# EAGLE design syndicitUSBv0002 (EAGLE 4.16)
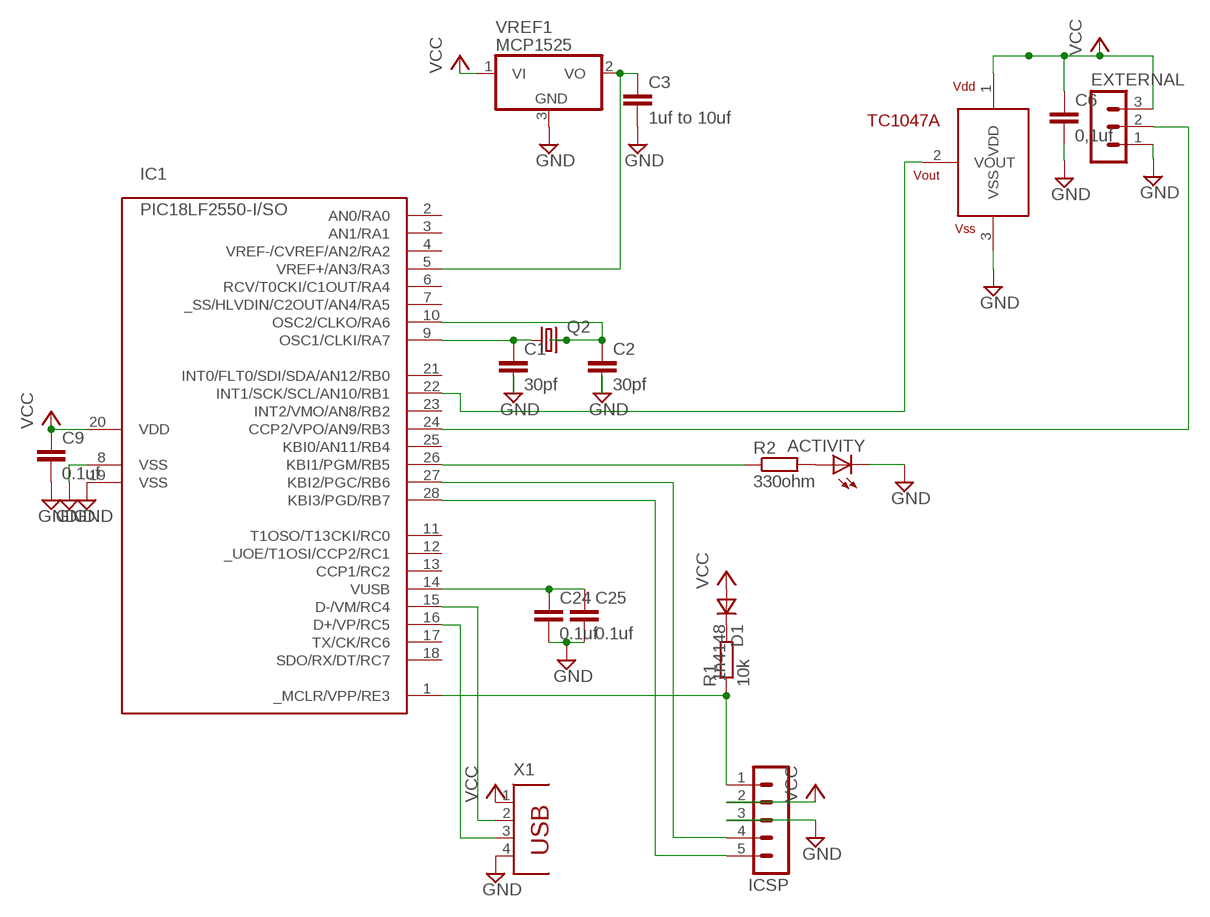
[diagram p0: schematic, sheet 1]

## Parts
ACTIVITY  LEDCHIPLED_1206  [CHIPLED_1206]
C1  30pf  C-EUC0805K  [C0805K]
C2  30pf  C-EUC0805K  [C0805K]
C3  1uf to 10uf  C-EUC0805K  [C0805K]
C6  0,1uf  C-EUC0805  [C0805]
C9  0.1uf  C-EUC0805K  [C0805K]
C24  0.1uf  C-EUC0805K  [C0805K]
C25  0.1uf  C-EUC0805K  [C0805K]
D1  1n4148  DSOT23  [SOT-23]
EXTERNAL  MA03-1  [MA03-1]
IC1  PIC18LF2550-I/SO  [SO-28W]
ICSP  MA05-1  [MA05-1]
Q2  CRYTALHC49UP  [HC49UP]
R1  10k  R-EU_R1206  [R1206]
R2  330ohm  R-EU_R0805  [R0805]
TC1047A  TC1047A  [SOT23B]
VREF1  MCP1525  MCP1525-SOT23  [SOT23]
X1  PN61729  [PN61729]

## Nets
GND: ACTIVITY.C C1.2 C2.2 C3.2 C6.2 C9.2 C24.2 C25.2 EXTERNAL.1 IC1.8(VSS) IC1.19(VSS) ICSP.3 TC1047A.3(VSS) VREF1.3(GND) X1.4
N$1: C1.1 IC1.9(OSC1/CLKI/RA7) Q2.1
N$2: C2.1 IC1.10(OSC2/CLKO/RA6) Q2.2
N$5: C24.1 C25.1 IC1.14(VUSB)
N$6: C3.1 IC1.5(VREF+/AN3/RA3) VREF1.2(VO)
N$7: IC1.27(KBI2/PGC/RB6) ICSP.4
N$8: IC1.28(KBI3/PGD/RB7) ICSP.5
N$9: D1.1(C) R1.2
N$10: IC1.1(_MCLR/VPP/RE3) ICSP.1 R1.1
N$11: EXTERNAL.2 IC1.24(CCP2/VPO/AN9/RB3)
N$12: ACTIVITY.A R2.2
N$14: IC1.26(KBI1/PGM/RB5) R2.1
N$23: IC1.15(D-/VM/RC4) X1.2
N$24: IC1.16(D+/VP/RC5) X1.3
N$44: IC1.22(INT1/SCK/SCL/AN10/RB1) TC1047A.2(VOUT)
VCC: C6.1 C9.1 D1.3(A) EXTERNAL.3 IC1.20(VDD) ICSP.2 TC1047A.1(VDD) VREF1.1(VI) X1.1
Unconnected: IC1.2(AN0/RA0) IC1.3(AN1/RA1) IC1.4(VREF-/CVREF/AN2/RA2) IC1.6(RCV/T0CKI/C1OUT/RA4) IC1.7(_SS/HLVDIN/C2OUT/AN4/RA5) IC1.11(T1OSO/T13CKI/RC0) IC1.12(_UOE/T1OSI/CCP2/RC1) IC1.13(CCP1/RC2) IC1.17(TX/CK/RC6) IC1.18(SDO/RX/DT/RC7) IC1.21(INT0/FLT0/SDI/SDA/AN12/RB0) IC1.23(INT2/VMO/AN8/RB2) IC1.25(KBI0/AN11/RB4)

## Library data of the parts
ACTIVITY = led:LED: LED
C1-C3 C6 C9 C24 C25 = rcl:C-EU: CAPACITOR, European symbol
D1 = zetex:D: DIODE
EXTERNAL = con-lstb:MA03-1: PIN HEADER
IC1 = microchip-pic18fxx5x:PIC18*2550: PIC18*2550 Microchip FLASH Microcontroller with FS-USB DEVICE FEATURES FeaturePIC18*2550 Program Memory (bytes) 32k Program Memory (instructions) 16384 I/O Ports Ports A, B, C, (E) Capture/Compare/PWM Modules 2 Enhanced Capture/Compare/PWM Modules 0 Parallel Communications (PSP) No 10-bit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
ICSP = con-lstb:MA05-1: PIN HEADER
Q2 = crystal:CRYTAL: CRYSTAL
R1 R2 = rcl:R-EU_: RESISTOR, European symbol
TC1047A = syndicitUSB:TC1047A
VREF1 = syndicitUSB:MCP1525-SOT23
X1 = con-berg:PN61729: BERG USB connector

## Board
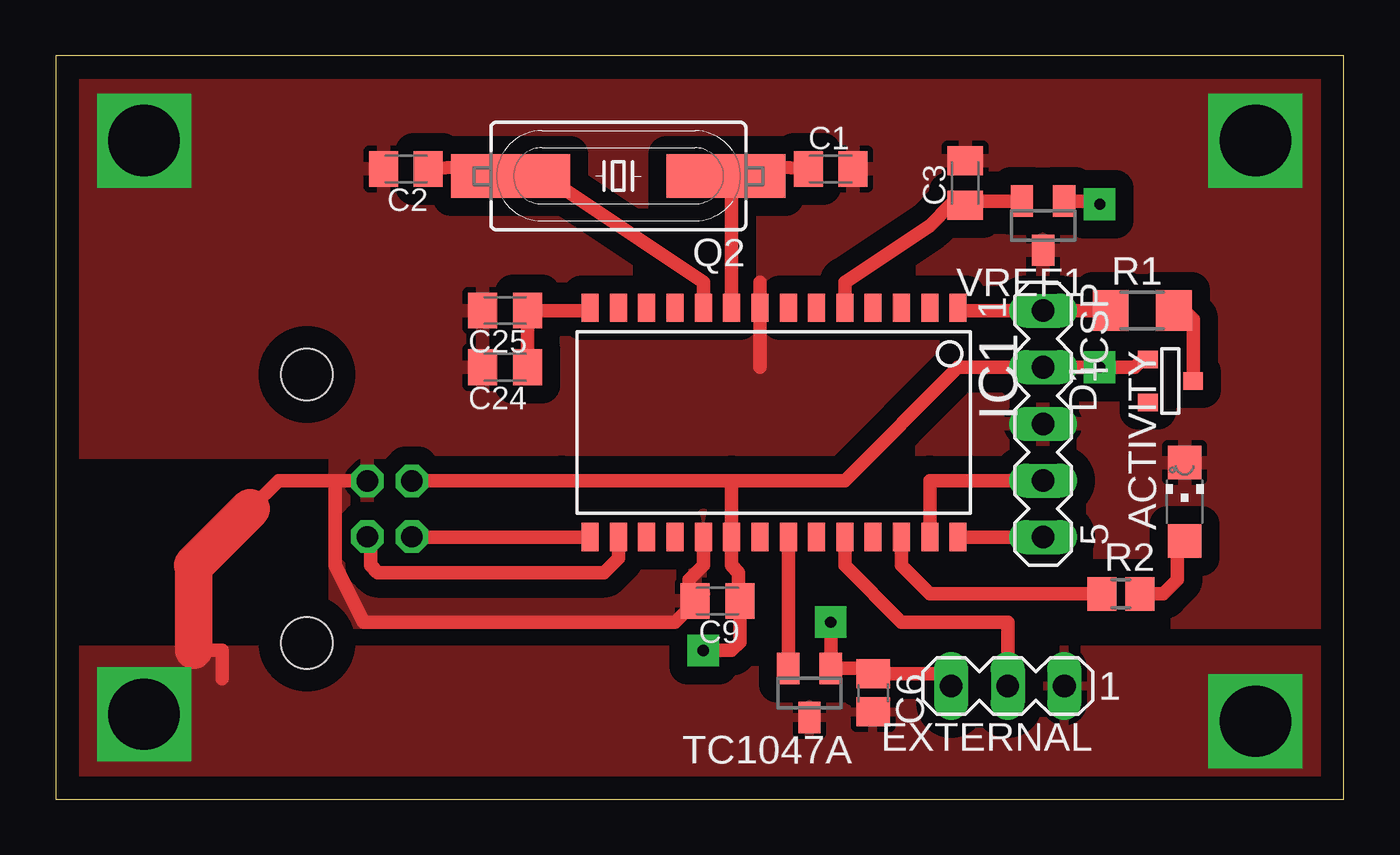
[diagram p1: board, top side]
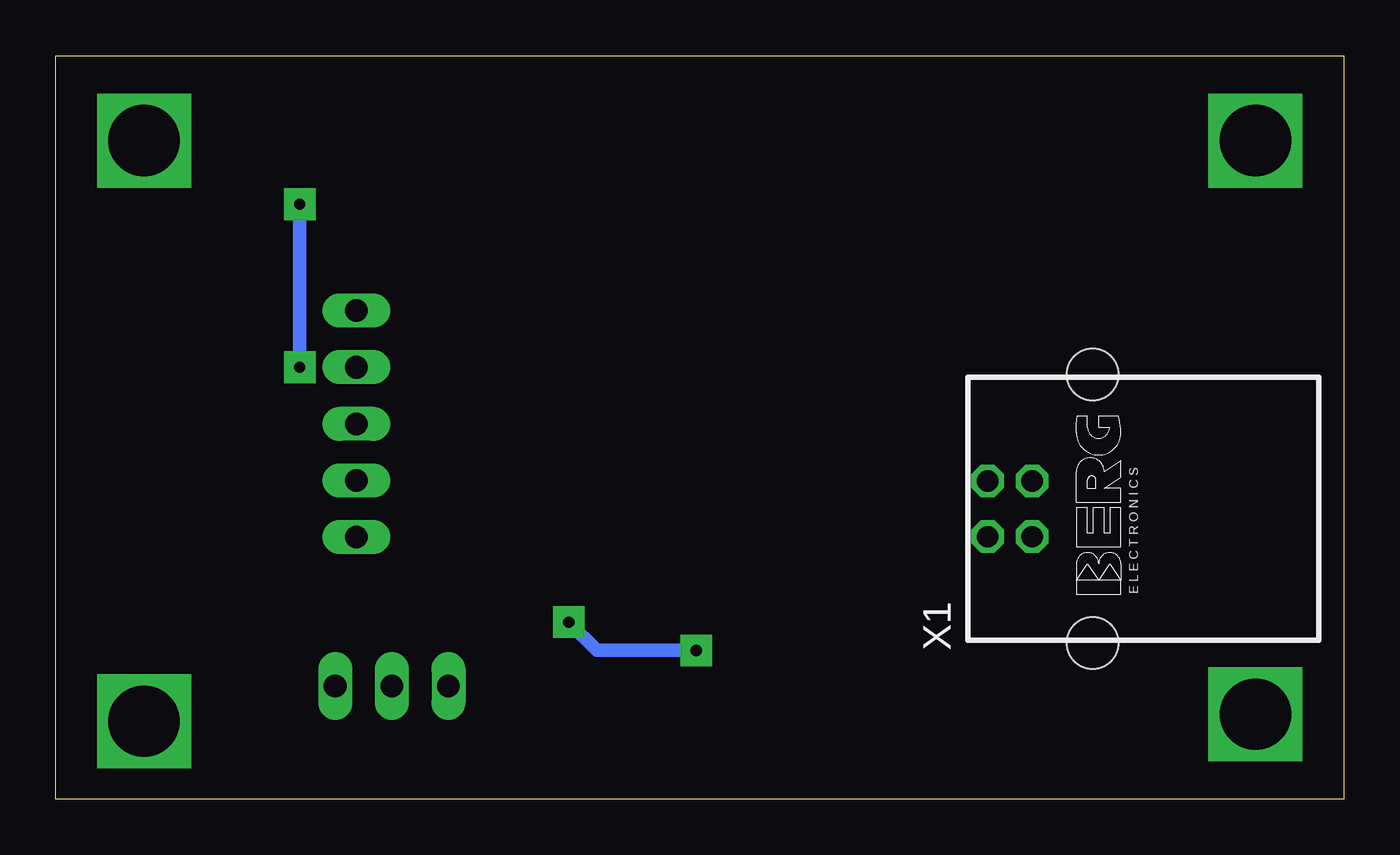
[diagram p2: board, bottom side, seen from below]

Size 57.77 x 33.33 mm. Coordinates in mm from the lower left corner, seen from the top.
Outline: 57.77,33.33 0,33.33 0,0 57.77,0 57.77,33.33
Copper layers (1*16): Top 0.035mm / dielectric 1.5mm / Bottom 0.035mm
Design rules "default": minimum track width 10mil, minimum drill 24mil, track to track 8mil, track to pad 8mil, pad to pad 8mil, via to via 8mil, smd to smd 8mil, copper to edge 40mil, drill to drill 8mil, minimum pad ring 10mil, minimum via ring 8mil, stop-mask expansion 4mil, vias tented up to drill 0mil, thermal gap 10mil

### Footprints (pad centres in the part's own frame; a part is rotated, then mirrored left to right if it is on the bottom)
CHIPLED_1206 = smd 1.5 x 1.5: A 0,-1.75; C 0,1.75
C0805K = smd 1.3 x 1.6: 1 -1,0; 2 1,0
C0805 = smd 1.3 x 1.5: 1 -0.85,0; 2 0.85,0
SOT-23 = smd 0.787 x 0.889: 1 0.025,-1.016; 2 -0.94,1.016; 3 0.991,1.016
MA03-1 = drill 1.016 long: 1 -2.54,0; 2 0,0; 3 2.54,0
SO-28W = smd 0.762 x 1.27: 1 -7.62,-5.207; 2 -6.35,-5.207; 3 -5.08,-5.207; 4 -3.81,-5.207; 5 -2.54,-5.207; 6 -1.27,-5.207; 7 0,-5.207; 8 1.27,-5.207; 9 2.54,-5.207; 10 3.81,-5.207; 11 5.08,-5.207; 12 6.35,-5.207; 13 7.62,-5.207; 14 8.89,-5.207; 15 8.89,5.08; 16 7.62,5.08; 17 6.35,5.08; 18 5.08,5.08; 19 3.81,5.08; 20 2.54,5.08; 21 1.27,5.08; 22 0,5.08; 23 -1.27,5.08; 24 -2.54,5.08; 25 -3.81,5.08; 26 -5.08,5.08; 27 -6.35,5.08; 28 -7.62,5.08
MA05-1 = drill 1.016 long: 1 -5.08,0; 2 -2.54,0; 3 0,0; 4 2.54,0; 5 5.08,0
HC49UP = smd 5.334 x 1.93: 1 -4.826,0; 2 4.826,0
R1206 = smd 1.6 x 1.803: 1 -1.422,0; 2 1.422,0
R0805 = smd 1.3 x 1.5: 1 -0.85,0; 2 0.85,0
SOT23B = smd 1 x 1.4: 1 -0.95,-1.1; 2 0.95,-1.1; 3 0,1.1
SOT23 = smd 1 x 1.4: 1 -0.95,-1.1; 2 0.95,-1.1; 3 0,1.1
PN61729 = drill 0.95 octagon: 1 1.25,4.71; 2 -1.25,4.71; 3 -1.25,2.71; 4 1.25,2.71 | hole 2.3: -6.02,0; 6.02,0

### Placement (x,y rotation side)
ACTIVITY  50.64,13.33 0 top
C1  34.76,28.25 0 top
C2  15.71,28.25 180 top
C3  40.79,27.62 90 top
C6  36.66,4.76 270 top
C9  29.68,8.88 180 top
C24  20.16,19.36 180 top
C25  20.16,21.9 180 top
D1  50,18.73 90 top
EXTERNAL  42.7,5.07 180 top
IC1  32.86,16.82 180 top
ICSP  44.29,16.82 270 top
Q2  25.23,27.94 180 top
R1  48.73,21.9 0 top
R2  47.78,9.2 0 top
TC1047A  33.81,4.76 180 top
VREF1  44.29,25.71 180 top
X1  11.27,13.01 90 bottom

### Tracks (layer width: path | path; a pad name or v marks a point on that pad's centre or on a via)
GND  (via drill 3.2)
  Top 0.61: 12.54,14.28 13.81,14.28 | 12.54,14.28 12.54,10.47 13.81,7.93 27.77,7.93 28.73,8.89 | 28.73,8.89 29.05,9.2 | 12.54,14.28 9.99,14.28 8.72,13.01 | 6.19,6.66 7.46,6.66 7.46,5.39 | IC1.19 29.05,10.47 28.41,9.84 28.41,9.2 28.73,8.89 | 28.73,8.89 C9.2 | 31.59,19.36 IC1.8 31.59,23.17
  Top 0.813: 13.81,14.28 13.83,14.26 X1.4
  Top 1.676: 6.19,6.66 6.19,10.47
  Top 1.778: 6.19,10.47 8.72,13.01
  other vias: 53.81,3.49 3.96,3.81 3.96,29.52 53.81,29.52
  pour Top (isolate 0.813): 58.26,6.66 0.79,6.66 0.79,0.31 58.26,0.31
  pour Top (isolate 0.813): 56.98,7.93 12.54,7.93 12.54,15.55 1.1,15.55 1.1,32.06 56.98,32.06
N$1
  Top 0.406: IC1.9 30.32,21.9 | 30.5,28.44 30.32,28.25 30.06,28 Q2.1
  Top 0.61: 30.5,28.44 C1.1 | IC1.9 30.32,28.25
N$2
  Top 0.406: 20.16,28.25 21.42,28.25 | 20.16,28.25 20.41,28 Q2.2 | 19.97,28.44 20.16,28.25
  Top 0.61: IC1.10 29.05,23.17 21.42,28.25 | C2.1 19.97,28.44
N$5
  Top 0.61: C24.1 21.16,21.63 21.42,21.9 C25.1 23.97,21.9 IC1.14
N$6
  Top 0.61: 40.65,26.81 40.79,26.67 C3.1 40.11,26.62 39.2,25.71 35.4,23.17 IC1.5 35.4,21.9 | 40.65,26.81 VREF1.2 | 40.65,26.81 40.48,26.98
N$7
  Top 0.406: 39.18,11.72 IC1.27
  Top 0.61: ICSP.4 39.2,14.28 IC1.27
N$8
  Top 0.61: IC1.28 ICSP.5
N$9
  Top 0.61: R1.2 50.64,21.9 51.02,21.52 D1.1
N$10
  Top 0.406: IC1.1 40.48,21.9
  Top 0.61: 40.48,21.9 ICSP.1 R1.1
N$11
  Top 0.61: EXTERNAL.2 42.7,7.93 37.94,7.93 35.4,10.47 IC1.24
N$12
  Top 0.61: R2.2 49.68,9.2 50.32,9.84 50.32,11.42 50.47,11.58 ACTIVITY.A
N$14
  Top 0.61: R2.1 39.2,9.2 37.94,10.47 IC1.26
N$23
  Top 0.61: X1.2 16.33,11.76 16.34,11.74 IC1.15
N$24
  Top 0.61: IC1.16 25.23,10.79 24.6,10.15 14.44,10.15 14.12,10.47 14.12,11.74 14.1,11.76 X1.3
N$44
  Top 0.61: TC1047A.2 32.86,10.15 IC1.22
VCC  (via drill 0.5 pad 1.42)
  Top 0.406: EXTERNAL.3 40.48,5.39 40.26,5.61
  Top 0.61: 30.32,14.28 IC1.20 30.32,10.47 30.63,10.15 30.63,8.89 C9.1 30.68,7.03 30.32,6.66 v29.05,6.66 | 30.32,14.28 35.4,14.28 40.48,19.36 ICSP.2 v46.83,19.36 48.41,19.36 48.77,19.72 D1.3 | X1.1 22.67,14.26 22.7,14.28 30.32,14.28 | 40.26,5.61 C6.1 36.66,5.39 36.2,5.86 TC1047A.1 34.76,6.03 v34.76,7.93 | VREF1.1 46.36,26.81 v46.83,26.67
  Bottom 0.61: v29.05,6.66 33.49,6.66 v34.76,7.93 | v46.83,19.36 v46.83,26.67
